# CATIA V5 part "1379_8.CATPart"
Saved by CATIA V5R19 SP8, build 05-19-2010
Part number: 8
Bounding box of the stored display mesh (mm): x -2 to 1, y 11.5 to 30.489, z -12 to -2.25
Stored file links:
  C:\Users\ThinkMotion\Desktop\EU_thinkMotion\iao\IAO_MMS_Groupe3\bblot\bblot\1379_8.CATPart
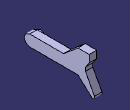
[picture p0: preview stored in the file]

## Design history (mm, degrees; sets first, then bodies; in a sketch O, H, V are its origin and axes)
Body1 (main body)
  Point1 to Point5: stored without definition
  Sketch1 on yz-plane, origin (0, 0, 0), H (0, 1, 0), V (0, 0, 1)
    line L1 (13, -5.5) -> (22.1268, -5.5)
    line L2 (22.1268, -5.5) -> (26, -2.25)
    line L3 (26, -2.25) -> (29, -2.25)
    line L4 (29, -2.25) -> (29, -4.25)
    line L5 (29, -4.25) -> (28, -5.6781)
    line L6 (28, -5.6781) -> (28, -6.6781)
    line L7 (28, -6.6781) -> (30.4414, -11.2651)
    line L8 (29.6615, -11.868) -> (26, -8.5)
    line L9 (26, -8.5) -> (13, -8.5)
    arc A1 centre (13, -7) radius 1.5 from (13, -8.5) to (13, -5.5) cw
    point P10 (13, -7)
    reference projected point E1 (13, -7) from Point1
    arc A2 centre (30, -11.5) radius 0.5 from (30.4414, -11.2651) to (29.6615, -11.868) cw
    axis line L10 (30, -12) -> (28.1146, -12)
    point P14 (30, -12)
    reference projected point E2 (13, -7) from Point2
    reference projected point E3 (13, -7) from Point3
    reference projected point E4 (13, -7) from Point4
    reference projected point E5 (13, -7) from Point5
    distance L1 L9 = 3
    radius A2 = 0.5
    distance L10 E2 = 5
    distance L3 E3 = 4.75
    distance L4 E4 = 16
    angle L3 L2 = 40
    length L6 = 1
    angle L5 L4 = 35
    length L4 = 2
    distance L6 L4 = 1
    length L9 = 13
    distance P14 E5 H = 17
    length L3 = 3
    horizontal: L1 H, L3 H, L9 H, L10 H
    vertical: L4 V, L6 V
    tangency: A1 L9, A1 L1, A2 L7, A2 L8, L10 A2
    coincidence: P10 E1, P14 A2
  Pad1: profile Sketch1, direction (1, 0, 0), length 1, opposite side length 1
  Sketch2 on start face of Pad1, origin (-1, 0, 0), H (0, -1, 0), V (0, 0, 1)
    circle A1 centre (-13, -7) radius 1
    reference projected arc E1 centre (-13, -7) radius 1.5 from (-13, -8.5) to (-13, -5.5) ccw from edge [start face of Pad1 | face of Pad1 from Sketch1.A1]
    radius A1 = 1
    concentricity: A1 E1
  Pad2: profile Sketch2, direction (-1, 0, 0), length 1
